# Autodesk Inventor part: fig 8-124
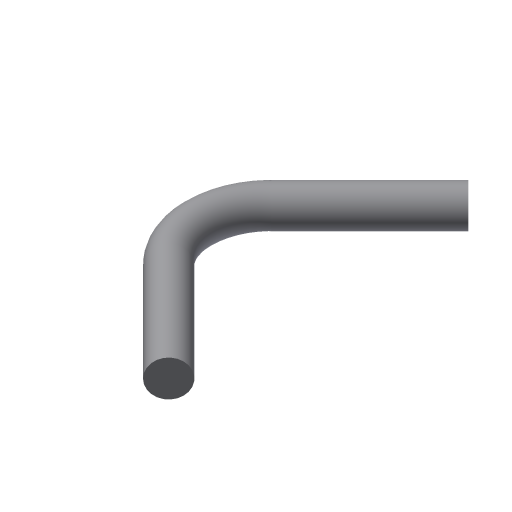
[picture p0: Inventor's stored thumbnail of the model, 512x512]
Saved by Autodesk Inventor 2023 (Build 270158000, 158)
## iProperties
Created: 2007-02
Part Number: fig 8-124
Document SubType Name: Modeling
Designer: Administrator
Density: 1 g/cm^3
Material: Generic
Appearance: Default
Author: Administrator
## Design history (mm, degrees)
node "Sketch1"
sketch "Sketch2"
  geometry: C1 r 5 at (0, 0); 1 further point
  constraints: 1 centre point, 1 coincident, 1 other
  dimensions: "d0" = 10 diameter of C1
extrude "Extrusion1" new body sketch "Sketch2" stored distance "d1" = 100; taper "d2" = 0 deg
workplane "Work Plane1"
sketch "Sketch3"
  geometry: L1 (0, 11)-(0, -8)
  constraints: 2 end point, 1 vertical
feature "Bend Part2" sketch "Sketch3" dims "d5" = 15, "d6" = 90 deg
body "Solid1"
